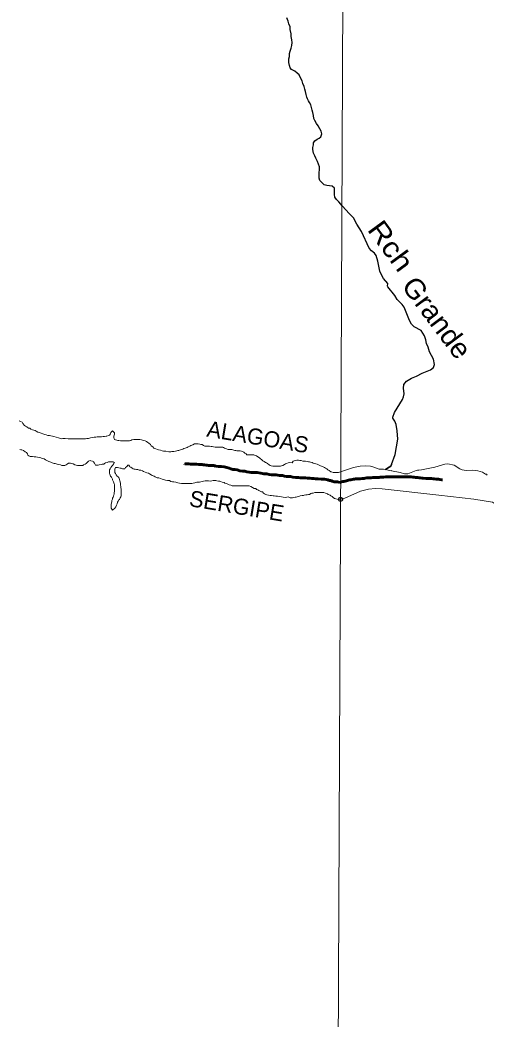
# Model space of a CAD drawing. Extents: x 553962 to 842807, y 8883888 to 9032388.
# Drawn here: x 656534 to 668185, y 8908836 to 8933785 of the extents above; entities that cross this region are included whole.
import ezdxf
from ezdxf.enums import TextEntityAlignment as Align

# ---------------------------------------------------------------- set-up
doc = ezdxf.new("R2010")
doc.units = 0
doc.header["$LTSCALE"] = 200
doc.header["$PDMODE"] = 32
doc.header["$PDSIZE"] = 100
doc.linetypes.add('LONG_DASH_SHORT_DASH', pattern=[9.9, 6, -1.2, 1.5, -1.2])
for name, color, linetype, lineweight in [('1', 7, 'Continuous', 13), ('24', 7, 'Continuous', 25), ('25', 7, 'Continuous', 13), ('7', 7, 'LONG_DASH_SHORT_DASH', 60)]:
    doc.layers.add(name, color=color, linetype=linetype, lineweight=lineweight)
doc.layers.add('42', color=7, linetype='Continuous')
doc.layers.add('49', color=7, linetype='Continuous')

msp = doc.modelspace()

# ---------------------------------------------------------------- linework, layer by layer
at = {"layer": '1'}
msp.add_lwpolyline([(664968.2, 9023436.8), (664657.1, 8949509), (664397.1, 8890880.2)], dxfattribs=at)
at = {"layer": '24'}
msp.add_line((666737.2, 8925710.7), (666737.9, 8925710.1), dxfattribs=at)
for points in [[(663996.4, 8929884.7), (663996.8, 8929971.2), (664009.7, 8930053.7), (664007.4, 8930113.8), (663977.7, 8930184), (663958, 8930249.2), (663913.4, 8930334.5), (663886.1, 8930392.2), (663858.9, 8930462.4), (663839.3, 8930550.1), (663839.5, 8930602.7), (663854.8, 8930667.7), (663860.1, 8930715.2), (663887.8, 8930767.6), (663945.6, 8930807.4), (663995.7, 8930834.6), (664041, 8930869.4), (664061.3, 8930941.9), (664046.6, 8931004.6), (664011.8, 8931064.8), (663969.6, 8931137.6), (663929.9, 8931197.9), (663890.2, 8931270.7), (663862.9, 8931320.8), (663855.7, 8931401), (663836.1, 8931476.2), (663821.3, 8931533.8), (663804.1, 8931601.4), (663786.9, 8931666.6), (663759.6, 8931724.3), (663734.8, 8931769.5), (663707.5, 8931812.2), (663690.2, 8931859.8), (663675.5, 8931924.9), (663658.3, 8932002.6), (663638.6, 8932057.8), (663621.3, 8932120.4), (663589.2, 8932200.7), (663572, 8932265.8), (663534.8, 8932343.6), (663497.6, 8932413.9), (663447.7, 8932454.2), (663390.4, 8932504.5), (663310.5, 8932545), (663277, 8932589.1), (663254.9, 8932645.9), (663239.1, 8932721.7), (663245.4, 8932772.2), (663244.2, 8932810.6), (663254.5, 8932873.1), (663257.3, 8932950.7), (663275.1, 8933003.2), (663298, 8933083.1), (663318.3, 8933145.6), (663321.2, 8933225.6), (663319, 8933288.2), (663299.3, 8933375.9), (663297.1, 8933436), (663277.6, 8933543.7), (663272.9, 8933611.3), (663240.7, 8933686.5), (663226, 8933756.7), (663191.4, 8933839.4)], [(665884.6, 8926902.1), (665710.7, 8927118.6), (665703.5, 8927141.6), (665707.3, 8927207.3), (665604.7, 8927327.2), (665543.5, 8927435.1), (665514.2, 8927508.8), (665462.2, 8927764.8), (665420, 8927905.9), (665377.5, 8927963.9), (665304.4, 8928016.2), (665243.3, 8928087.8), (665050.8, 8928503.2), (664941.5, 8928686.6), (664858.3, 8928844.6), (664746.5, 8928950.8), (664577.8, 8929135.4), (664488.9, 8929245.3), (664434.1, 8929300.7), (664391.8, 8929358.5), (664382.1, 8929428.6), (664380, 8929511.2), (664377.8, 8929583.8), (664325.5, 8929634.1), (664258, 8929647), (664193, 8929654.8), (664125.5, 8929670.2), (664070.7, 8929720.5), (664013.4, 8929773.4), (663996.1, 8929836.1), (663996.4, 8929884.7)], [(665654.1, 8922558.1), (665747.4, 8922613.4), (665782.6, 8922644.9), (665804.2, 8922685), (665898.2, 8922937), (665956.6, 8923316.8), (665944.3, 8923521), (665915.9, 8923680.3), (665887.1, 8923762.6), (665837.8, 8923840.4), (665834.9, 8923868.6), (665876, 8923981.1), (666075.9, 8924311.2), (666104.4, 8924374.8), (666118.2, 8924447.8), (666103.2, 8924589.1), (666111.8, 8924680), (666180.2, 8924767.7), (666303.3, 8924840.7), (666423.2, 8924888.8), (666567, 8924965.4), (666778.1, 8925046.5), (666849.4, 8925104.6), (666875.5, 8925182.5), (666852.3, 8925317.2), (666747.4, 8925494.9), (666714.9, 8925611.2), (666674, 8925709.5), (666660.9, 8925800.8), (666626.8, 8925897.6), (666539.3, 8926027.5), (666367.3, 8926123.4), (666298.2, 8926188.4), (666251.5, 8926283.4), (666120.6, 8926610.3), (666067.4, 8926681.3), (665942.6, 8926807.9), (665884.6, 8926902.1)], [(665804.2, 8922685), (665782.6, 8922644.9), (665747.4, 8922613.4), (665654.1, 8922558.1)]]:
    msp.add_lwpolyline(points, dxfattribs=at)
msp.add_point((664531.1, 8921815.4), dxfattribs=at)
at = {"layer": '25'}
for points in [[(656515.3, 8923772.7), (656550.1, 8923754.9)], [(656550.1, 8923754.9), (656587.5, 8923737.1), (656607.3, 8923704.5), (656647, 8923661.6), (656671.8, 8923641.4), (656706.7, 8923623.7), (656744, 8923593.4), (656779, 8923588.2), (656803.8, 8923570.5), (656848.7, 8923552.7), (656876.1, 8923537.4), (656908.6, 8923532.2), (656936, 8923517), (656975.8, 8923491.7), (657013.3, 8923486.5), (657063.2, 8923466.1), (657105.6, 8923450.8), (657153, 8923435.5), (657190.4, 8923427.7), (657230.3, 8923409.9), (657272.8, 8923404.6), (657302.8, 8923399.4), (657345.2, 8923394.1), (657377.7, 8923381.4), (657437.6, 8923363.5), (657495, 8923348.1), (657577.3, 8923327.5), (657604.9, 8923329.8), (657624.9, 8923329.7), (657664.9, 8923329.4), (657732.4, 8923329), (657805, 8923328.5), (657862.5, 8923328.1), (657887.5, 8923328), (657925, 8923327.7), (657945, 8923327.6), (657992.5, 8923327.3), (658027.5, 8923327), (658082.6, 8923326.7), (658110.1, 8923326.5), (658167.6, 8923326.1), (658197.7, 8923333.4), (658242.7, 8923333.1), (658290.3, 8923352.8), (658337.9, 8923360), (658383, 8923364.7), (658428, 8923369.5), (658460.6, 8923374.2), (658518.2, 8923378.9), (658568.2, 8923378.5), (658610.7, 8923380.8), (658645.7, 8923383), (658680.8, 8923387.8), (658700.8, 8923390.2), (658741, 8923407.4), (658768.6, 8923417.3), (658791.3, 8923452.2), (658801.5, 8923479.6), (658839.4, 8923524.4), (658894.1, 8923476.5), (658893.8, 8923444), (658886.1, 8923419), (658878.4, 8923391.5), (658878.2, 8923371.5), (658878.1, 8923351.4), (658883, 8923331.4), (658895.3, 8923311.3), (658917.7, 8923298.6), (658952.7, 8923290.9), (658975.1, 8923285.7), (658997.6, 8923280.6), (659045.1, 8923272.7), (659075.1, 8923272.5), (659120.1, 8923272.2), (659142.6, 8923272.1), (659177.6, 8923271.9), (659200.1, 8923271.7), (659240.2, 8923273.9), (659262.7, 8923278.8), (659295.3, 8923283.6), (659327.9, 8923300.9), (659370.5, 8923308.1), (659425.5, 8923310.3), (659473.1, 8923310), (659528.1, 8923307.1), (659565.5, 8923299.3), (659617.9, 8923284), (659655.3, 8923271.2), (659690.2, 8923256), (659720.1, 8923235.7), (659752.5, 8923218), (659789.7, 8923185.2), (659807, 8923147.5), (659849.3, 8923124.7), (659876.6, 8923094.5), (659919, 8923074.2), (659963.8, 8923056.4), (659988.8, 8923048.7), (660038.8, 8923043.3), (660078.7, 8923025.6), (660111.1, 8923015.3)], [(660111.1, 8923015.3), (660173.6, 8923017.4), (660243.5, 8922999.4), (660281.1, 8923004.2), (660301.1, 8923004.1), (660323.6, 8923006.4), (660356.1, 8923006.2), (660376.2, 8923008.6), (660411.2, 8923018.4), (660448.8, 8923023.1), (660471.4, 8923030.5), (660493.9, 8923037.8), (660516.5, 8923042.7), (660536.6, 8923052.6), (660564.1, 8923059.9), (660596.7, 8923069.7), (660624.3, 8923084.5), (660656.9, 8923089.3), (660704.6, 8923109.1), (660729.7, 8923126.4), (660774.9, 8923143.6), (660797.5, 8923161), (660842.6, 8923175.7), (660885.3, 8923198), (660915.3, 8923197.8), (660940.3, 8923197.6), (660980.4, 8923197.3), (661020.4, 8923194.6), (661042.8, 8923186.9), (661077.8, 8923181.7), (661115.1, 8923156.4), (661147.5, 8923138.7), (661187.5, 8923138.4), (661207.5, 8923138.3), (661245, 8923138), (661265, 8923137.9), (661305, 8923132.6), (661327.5, 8923130), (661365, 8923127.2), (661407.5, 8923119.4), (661447.5, 8923119.2), (661472.5, 8923119), (661507.5, 8923118.8), (661557.5, 8923115.9), (661592.5, 8923113.2), (661615, 8923110.5), (661637.4, 8923095.4), (661667.3, 8923087.7), (661702.2, 8923067.4), (661724.6, 8923057.2), (661754.6, 8923057), (661819.7, 8923056.6), (661897, 8923033.6), (661919.5, 8923030.9), (661942, 8923025.8), (661972, 8923023.1), (662009.5, 8923022.8), (662029.5, 8923022.7), (662062, 8923019.9), (662086.9, 8923009.8), (662121.8, 8922992), (662141.6, 8922969.4), (662176.5, 8922954.1), (662193.8, 8922928.9), (662226.3, 8922923.7), (662258.8, 8922923.5), (662293.8, 8922923.3), (662313.9, 8922923.2), (662333.9, 8922923), (662371.4, 8922922.8), (662401.3, 8922912.6), (662438.7, 8922899.8), (662471.1, 8922879.6), (662508.4, 8922854.3), (662530.7, 8922824.1), (662563.1, 8922808.8), (662592.9, 8922776.1), (662625.2, 8922758.4), (662657.6, 8922738.1), (662680, 8922728), (662712.4, 8922707.7), (662747.2, 8922674.9), (662777.1, 8922659.7), (662804.5, 8922652), (662839.5, 8922644.3), (662884.5, 8922639), (662917, 8922638.8), (662937, 8922638.6), (662969.5, 8922638.4), (662992, 8922640.8), (663032.1, 8922645.5), (663054.6, 8922652.9), (663094.7, 8922662.6), (663134.9, 8922679.9), (663155, 8922697.3), (663182.6, 8922712.1), (663225.3, 8922729.4), (663250.3, 8922734.2), (663325.3, 8922723.7), (663348.2, 8922771.1), (663378.2, 8922778.4)], [(658100, 8922655.6), (658065, 8922655.8), (658042.5, 8922656), (657999.9, 8922656.3), (657972.4, 8922659), (657932.5, 8922666.7), (657900.1, 8922679.5), (657860.2, 8922702.3), (657820.2, 8922707.5), (657797.8, 8922715.2), (657762.8, 8922715.4), (657742.8, 8922715.6), (657707.6, 8922693.3), (657684.9, 8922673.4), (657649.8, 8922656.1), (657629.8, 8922656.2), (657609.8, 8922656.3), (657577.2, 8922656.6), (657542.3, 8922671.8), (657499.9, 8922682.1), (657460, 8922689.9), (657415.1, 8922707.7), (657382.6, 8922712.9), (657335.2, 8922728.3), (657305.3, 8922746), (657255.4, 8922761.3), (657205.5, 8922781.7), (657168.1, 8922797), (657138.3, 8922824.7), (657085.9, 8922837.6), (657051, 8922852.8), (657011, 8922860.6), (656973.6, 8922868.4), (656928.6, 8922873.7), (656888.6, 8922878.9), (656848.6, 8922881.7), (656826.1, 8922881.8), (656786.2, 8922887.1), (656751.2, 8922897.4), (656731.4, 8922917.5), (656719.1, 8922952.7), (656696.8, 8922982.8), (656659.5, 8923003.1), (656619.7, 8923030.9), (656577.3, 8923048.7), (656554.8, 8923051.4), (656529.8, 8923056.6)], [(658980.7, 8922371.9), (659008, 8922339.2), (659017.7, 8922306.6), (659025, 8922274), (659032.3, 8922253.9), (659039.5, 8922208.8), (659041.8, 8922183.7), (659044.1, 8922163.7), (659046.5, 8922141.1), (659048.7, 8922108.6), (659055.9, 8922071), (659058.3, 8922050.9), (659058.1, 8922030.9), (659060.5, 8922010.9), (659060.3, 8921988.3), (659060.1, 8921955.8), (659059.8, 8921920.7), (659057.2, 8921900.7), (659047, 8921878.3), (659034.3, 8921853.3), (659021.6, 8921830.9), (659013.9, 8921808.4), (658991.3, 8921791), (658981.1, 8921766), (658970.9, 8921743.6), (658960.6, 8921703.6), (658945.3, 8921668.6), (658932.7, 8921646.2), (658922.5, 8921623.7), (658899.7, 8921591.3), (658844.4, 8921546.6), (658809.7, 8921594.4), (658807.5, 8921627), (658807.6, 8921649.5), (658807.9, 8921684.6), (658815.7, 8921724.6), (658823.4, 8921752.1), (658828.7, 8921787.1), (658838.9, 8921817.1), (658844.1, 8921842.1), (658856.8, 8921864.5), (658869.5, 8921894.5), (658874.8, 8921924.5), (658879.9, 8921947), (658882.7, 8921982), (658887.9, 8922012), (658888.2, 8922042), (658888.3, 8922064.6), (658888.6, 8922097.1), (658888.8, 8922132.2), (658889, 8922152.2), (658889.2, 8922182.2), (658884.4, 8922202.3), (658864.7, 8922247.5), (658859.9, 8922270.1), (658845.1, 8922297.7), (658842.7, 8922317.7), (658835.4, 8922337.8), (658818.1, 8922370.5), (658793.3, 8922393.2), (658786, 8922420.8), (658773.6, 8922440.9), (658771.3, 8922460.9), (658766.5, 8922493.5), (658766.8, 8922523.5), (658767, 8922548.6), (658784.7, 8922576), (658802.4, 8922608.4), (658827.7, 8922640.8), (658845.4, 8922663.2), (658863.1, 8922690.6), (658875.8, 8922718.1), (658896, 8922738), (658861, 8922748.2), (658836, 8922753.4), (658803.5, 8922753.6), (658778.5, 8922753.8), (658738.5, 8922754), (658705.8, 8922736.7), (658665.8, 8922729.5), (658645.6, 8922712.1), (658625.5, 8922694.7), (658603, 8922694.8), (658580.4, 8922690), (658560.4, 8922682.6), (658510.3, 8922675.4), (658485.2, 8922670.6), (658452.7, 8922668.3), (658417.7, 8922671), (658395.5, 8922713.7), (658375.7, 8922733.9), (658373.3, 8922753.9), (658343.4, 8922764.2), (658303.5, 8922779.4), (658281, 8922782.1), (658243.4, 8922767.3), (658223.2, 8922752.4), (658182.9, 8922712.7), (658162.8, 8922690.2), (658122.6, 8922673), (658100, 8922655.6)], [(662255.4, 8922147.4), (662220.4, 8922150.2), (662177.9, 8922153), (662152.9, 8922153.1), (662112.9, 8922153.4), (662087.9, 8922153.6), (662027.9, 8922154), (661975.4, 8922154.3), (661940.3, 8922154.5), (661900.3, 8922154.8), (661872.8, 8922155), (661830.3, 8922155.3), (661790.4, 8922170.6), (661750.4, 8922175.8), (661715.6, 8922196.1), (661683.2, 8922211.3), (661648.2, 8922221.6), (661625.8, 8922236.7), (661578.3, 8922242.1), (661538.5, 8922257.3), (661516, 8922265), (661483.5, 8922270.2), (661441.1, 8922278), (661416.1, 8922283.2), (661373.6, 8922283.5), (661351.1, 8922283.6), (661290.9, 8922269), (661233.5, 8922274.4), (661178.4, 8922274.7), (661150.9, 8922272.4), (661115.8, 8922267.6), (661075.8, 8922260.4), (661015.6, 8922243.3), (660945.6, 8922238.7), (660892.9, 8922224.1), (660852.8, 8922216.8), (660825.3, 8922212), (660772.8, 8922209.8), (660732.7, 8922210.1), (660682.7, 8922210.4), (660637.7, 8922210.7), (660610.2, 8922210.9), (660560.2, 8922211.2), (660510.2, 8922219.1), (660475.2, 8922226.8), (660425.4, 8922244.7), (660375.4, 8922247.5), (660342.9, 8922255.2), (660295.5, 8922263.1), (660268.1, 8922280.8), (660213.1, 8922286.1), (660165.6, 8922294), (660113.2, 8922309.3), (660080.8, 8922317.1), (660035.9, 8922332.4), (659996, 8922347.7), (659958.5, 8922352.9), (659936, 8922360.6), (659903.6, 8922375.8), (659878.8, 8922393.5), (659833.8, 8922408.8), (659809, 8922424), (659766.6, 8922449.3), (659739.3, 8922467), (659699.3, 8922472.3), (659656.9, 8922492.6), (659619.5, 8922505.4), (659587.1, 8922525.6), (659547.2, 8922538.4), (659509.8, 8922546.2), (659477.3, 8922556.4), (659442.3, 8922561.6), (659407.4, 8922566.8), (659382.4, 8922569.5), (659354.9, 8922577.2), (659330, 8922592.4), (659297.7, 8922615.2), (659275.2, 8922625.3), (659267.9, 8922645.4), (659245.6, 8922665.6), (659223.1, 8922668.2), (659210.4, 8922645.8), (659195.2, 8922623.3), (659170.1, 8922611), (659152.3, 8922576.1), (659117.3, 8922576.3), (659092.3, 8922573.9), (659059.9, 8922589.2), (659037.4, 8922594.3), (659002.5, 8922602.1), (658967.5, 8922607.3), (658945, 8922610), (658920, 8922605.1), (658902.2, 8922567.7), (658902, 8922540.2), (658899.2, 8922502.6), (658901.5, 8922482.6), (658913.8, 8922460), (658933.6, 8922427.3), (658955.8, 8922392.1), (658980.7, 8922371.9)], [(663378.2, 8922778.4), (663398.3, 8922785.8), (663440.8, 8922790.5), (663478.4, 8922790.3), (663513.3, 8922787.5), (663545.9, 8922787.3), (663588.2, 8922767), (663623.2, 8922764.3), (663658.2, 8922764.1), (663698.2, 8922761.3), (663730.7, 8922753.6), (663760.7, 8922748.3), (663785.6, 8922740.7), (663825.6, 8922735.4), (663850.5, 8922720.2), (663890.4, 8922704.9), (663912.8, 8922697.3), (663950.3, 8922692), (663977.7, 8922674.3), (664032.5, 8922648.9), (664084.9, 8922631), (664127.3, 8922608.2), (664152.1, 8922590.5), (664192, 8922572.8), (664211.9, 8922552.6), (664249.2, 8922534.8), (664286.5, 8922504.5), (664309, 8922496.9), (664348.9, 8922486.6), (664381.4, 8922481.4), (664416.4, 8922481.1), (664436.4, 8922481), (664461.5, 8922483.3), (664481.5, 8922483.2), (664531.1, 8922504.7), (664855.7, 8922606.1), (665018.2, 8922640.1), (665151.9, 8922649.8), (665276.6, 8922642.6), (665359.5, 8922619.8)], [(665359.5, 8922619.8), (665492.3, 8922568.3), (665600, 8922565.9), (665805.3, 8922529)], [(665807.2, 8922530.5), (665805.3, 8922529), (666021.2, 8922480.8), (666128.1, 8922448.4), (666212.6, 8922450.2), (666414.1, 8922533.6), (666451.7, 8922544.9), (666486.4, 8922546.2), (666551.6, 8922551.4), (666883.2, 8922619.3), (667134.9, 8922692.2), (667207.8, 8922696.8), (667366, 8922668.8), (667507, 8922579.6), (667567.9, 8922550.4), (667666.3, 8922536.7), (667827.1, 8922544.8), (667960.2, 8922528.3), (668076.2, 8922494.1), (668149.9, 8922444.5), (668175.3, 8922440.9), (668193.4, 8922414.2)], [(663096.2, 8921869), (663056.2, 8921876.8), (663013.8, 8921884.6), (662958.8, 8921889.9), (662913.8, 8921895.2), (662873.8, 8921898), (662851.3, 8921903.2), (662811.4, 8921908.4), (662773.9, 8921913.7), (662733.9, 8921921.5), (662696.5, 8921929.2), (662671.5, 8921936.9), (662634.1, 8921952.2), (662611.8, 8921972.3), (662586.9, 8921997.5), (662557, 8922002.8), (662529.6, 8922017.9), (662492.2, 8922033.2), (662469.8, 8922050.9), (662434.8, 8922056.1), (662415, 8922081.3), (662380, 8922084), (662332.7, 8922111.9), (662292.8, 8922132.2), (662255.4, 8922147.4)], [(670613, 8921062.4), (670594.6, 8921075.1), (670505.7, 8921092.1), (670378.9, 8921097.7), (670172.5, 8921136.1), (669790.2, 8921268), (669181.6, 8921455.5), (668940.4, 8921522.2), (668553.3, 8921609.1), (668470.6, 8921646), (668322.8, 8921739.3), (667855.1, 8921816.8), (666980.9, 8921915.9), (665565.9, 8922078.1), (665402.5, 8922087.8), (665227.8, 8922071.5), (665027.5, 8922015.6), (664640.9, 8921845.5), (664531.1, 8921815.4)], [(664531.1, 8921815.4), (664483.8, 8921807.2), (664446.4, 8921815), (664411.5, 8921827.8), (664379, 8921835.5), (664344.2, 8921863.2), (664321.8, 8921880.9), (664292, 8921903.7), (664269.6, 8921918.8), (664224.7, 8921936.6), (664202.3, 8921954.3), (664152.4, 8921969.7), (664117.5, 8921984.9), (664070, 8921987.7), (664027.5, 8921988), (663982.5, 8921988.3), (663937.5, 8921988.6), (663892.4, 8921983.9), (663849.7, 8921964.2), (663814.7, 8921964.4), (663792.2, 8921957), (663754.5, 8921937.2), (663734.5, 8921937.4), (663696.9, 8921930.1), (663661.8, 8921922.8), (663626.8, 8921915.6), (663606.7, 8921910.7), (663571.7, 8921905.9), (663524.1, 8921898.7), (663491.5, 8921883.9), (663446.4, 8921879.2), (663426.3, 8921871.8), (663396.3, 8921867), (663366.2, 8921857.2), (663333.7, 8921852.4), (663311.1, 8921850.1), (663276.1, 8921850.3), (663226.3, 8921875.7), (663156.2, 8921863.6), (663096.2, 8921869)]]:
    msp.add_lwpolyline(points, dxfattribs=at)
msp.add_point((664531.1, 8921815.4), dxfattribs=at)
at = {"layer": '7'}
for points in [[(663706.2, 8922345.6), (663656.3, 8922348.3), (663616.3, 8922351.1), (663591.3, 8922351.2), (663566.3, 8922353.8), (663526.3, 8922354), (663483.8, 8922356.8), (663411.3, 8922362.1), (663341.4, 8922367.5), (663281.5, 8922380.3), (663226.5, 8922383.1), (663181.5, 8922388.4), (663134.1, 8922393.7), (663081.6, 8922406.4), (663011.7, 8922409.3), (662926.8, 8922422.3), (662864.2, 8922422.6), (662806.8, 8922425.4), (662751.8, 8922430.7), (662691.9, 8922448.5), (662617, 8922453.9), (662539.5, 8922466.8), (662447.1, 8922482.4), (662372.1, 8922482.8), (662304.7, 8922488.1), (662249.7, 8922493.4), (662197.2, 8922498.7), (662142.3, 8922514), (662087.4, 8922516.8), (662020, 8922529.7), (661950.1, 8922547.6), (661892.6, 8922560.4), (661845.2, 8922563.1), (661797.8, 8922575.9), (661750.3, 8922591.1), (661690.5, 8922606.5), (661625.6, 8922621.8), (661563.1, 8922634.7), (661478.2, 8922637.6), (661413.2, 8922643), (661378.3, 8922655.7), (661338.3, 8922655.9), (661310.8, 8922656), (661268.3, 8922658.8), (661238.3, 8922661.4), (661205.8, 8922666.6), (661175.9, 8922669.3), (661135.9, 8922677), (661105.9, 8922679.6), (661076, 8922682.3), (661041, 8922687.5), (660993.5, 8922687.7), (660941, 8922690.5), (660893.5, 8922693.3), (660841, 8922693.6), (660786, 8922693.8), (660746, 8922696.6), (660718.5, 8922696.7), (660691.1, 8922701.8), (660648.6, 8922704.6), (660641.7, 8922706.3)], [(664555.3, 8922251.1), (664510.5, 8922233.7), (664455.6, 8922249), (664420.6, 8922251.7), (664375.7, 8922254.4), (664325.7, 8922267.2), (664288.3, 8922282.4), (664250.9, 8922287.6), (664213.5, 8922300.3), (664176, 8922305.6), (664128.6, 8922318.3), (664086.1, 8922318.5), (664048.6, 8922321.2), (663973.6, 8922324.1), (663908.6, 8922327), (663861.2, 8922332.2), (663816.2, 8922335), (663763.7, 8922340.3), (663706.2, 8922345.6)], [(666977.6, 8922317.6), (666919.1, 8922320.2), (666870.8, 8922327.8), (666842.8, 8922327.8), (666799.5, 8922330.4), (666761.3, 8922330.4), (666692.6, 8922335.5), (666657, 8922338), (666595.9, 8922340.6), (666565.4, 8922345.7), (666519.6, 8922348.3), (666496.7, 8922348.3), (666461.1, 8922355.9), (666440.7, 8922358.5), (666405.1, 8922361), (666366.9, 8922366.2), (666338.9, 8922371.3), (666290.6, 8922376.4), (666227, 8922376.4), (666168.5, 8922376.4), (666140.5, 8922376.4), (666092.1, 8922376.4), (666061.6, 8922376.4), (665980.2, 8922376.4), (665944.5, 8922376.4), (665886, 8922376.4), (665855.5, 8922376.4), (665799.5, 8922376.4), (665769, 8922376.4), (665697.7, 8922376.4), (665659.6, 8922376.4), (665601, 8922371.2), (665570.5, 8922368.7), (665519.6, 8922366.1), (665494.2, 8922361), (665443.3, 8922355.9), (665400, 8922355.9), (665377.1, 8922355.9), (665333.9, 8922355.9), (665293.2, 8922350.8), (665244.8, 8922350.8), (665188.8, 8922348.2), (665145.6, 8922340.6), (665122.7, 8922338), (665087.1, 8922335.5), (665066.7, 8922330.3), (665018.4, 8922327.8), (664987.8, 8922327.8), (664962.4, 8922327.8), (664934.4, 8922327.8), (664903.9, 8922327.8), (664875.9, 8922320.1), (664855.5, 8922320.1), (664819.9, 8922309.9), (664791.9, 8922304.8), (664763.9, 8922297.1), (664733.4, 8922289.4), (664708, 8922281.8), (664677.4, 8922276.7), (664646.9, 8922269), (664616.4, 8922261.3), (664585.8, 8922256.2), (664555.3, 8922251.1), (664555.3, 8922251.1), (664555.3, 8922251.1)], [(667073.5, 8922301.6), (667059.1, 8922304.8), (667005.6, 8922309.9), (666977.6, 8922317.6)]]:
    msp.add_lwpolyline(points, dxfattribs=at)

# ---------------------------------------------------------------- texts
at = {"layer": '42'}
for s, p in [('ALAGOAS', (662435, 8923174.8)), ('SERGIPE', (661908.6, 8921452.5))]:
    msp.add_text(s, height=400, rotation=350.533, dxfattribs=at).set_placement(p, align=Align.CENTER)
at = {"layer": '49'}
for s, rotation, width, p in [('Rch', 306.272, 1.15, (665180.9, 8928547.7)), ('Grande', 306.886, 1.05, (666032.2, 8927138.1))]:
    msp.add_text(s, height=500, rotation=rotation, dxfattribs=dict(at, width=width)).set_placement(p)

doc.saveas('drawing.dxf')
